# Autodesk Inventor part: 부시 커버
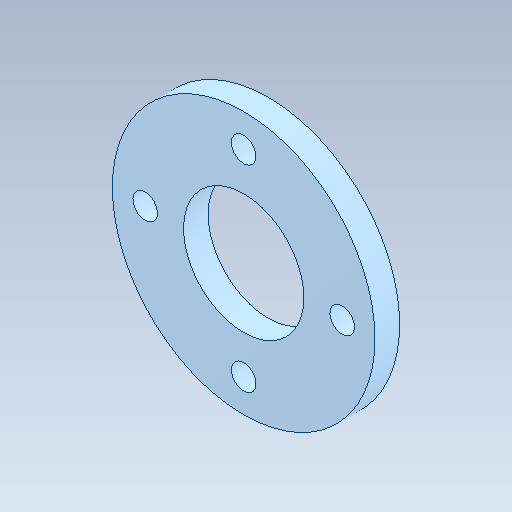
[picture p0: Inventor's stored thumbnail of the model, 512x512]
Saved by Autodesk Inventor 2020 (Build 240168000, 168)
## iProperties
Created: 2024-07
Part Number: 부시 커버
Material: 강철, 연강
Document SubType Name: Modeling
Designer: oem
Density: 7.85 g/cm^3
Appearance: 기본값
Author: jhkim
Sending System: Autodesk Inventor 2025
Preprocessor: ST-DEVELOPER v20
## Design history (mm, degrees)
feature "솔리드1"
node "솔리드2"
